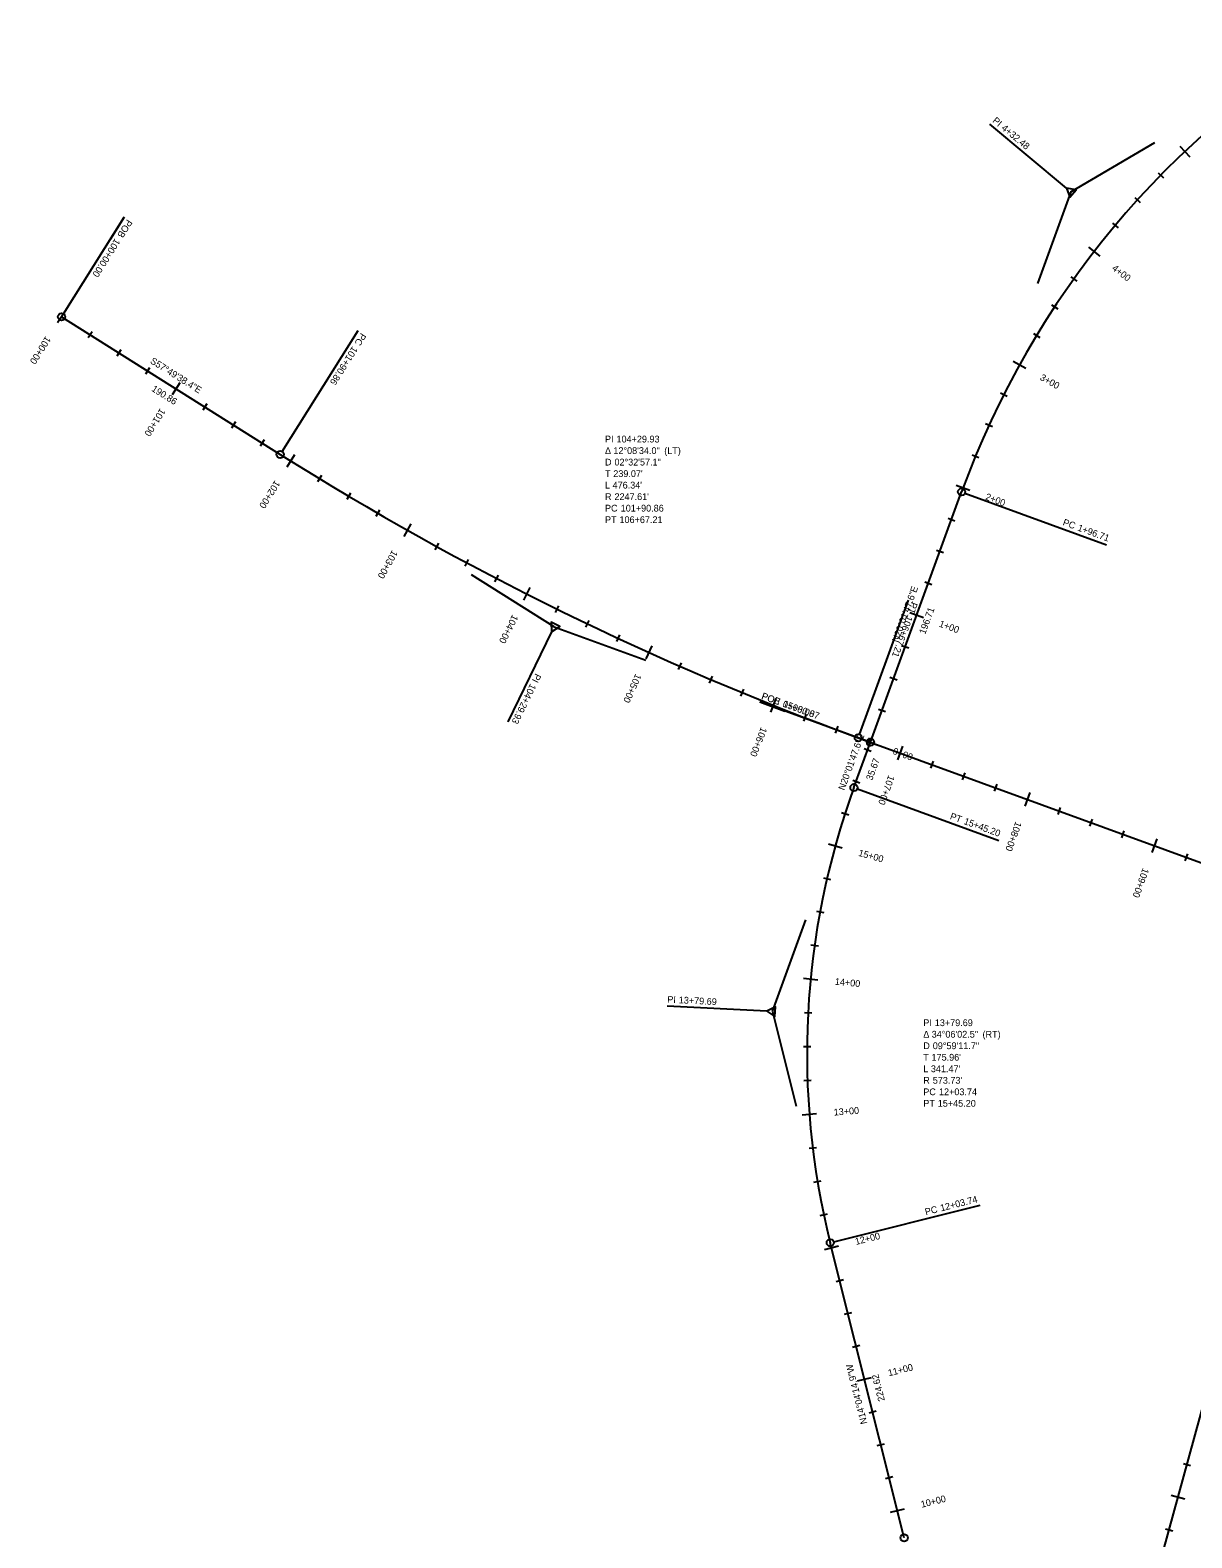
# Model space of a CAD drawing. Extents: x 2300830 to 2307917, y 756066 to 766359.
# Drawn here: x 2301963 to 2302821, y 761001 to 762114 of the extents above; entities that cross this region are included whole.
import ezdxf

# ---------------------------------------------------------------- set-up
doc = ezdxf.new("R2010")
doc.units = 0
for name, color, linetype in [('Default', 7, 'Continuous'), ('Draft_Bearing Label', 7, 'Continuous'), ('Draft_Curve Data Label', 7, 'Continuous'), ('Draft_Station Cardinal Lines', 7, 'Continuous'), ('Draft_Station Cardinal Points', 7, 'Continuous'), ('Draft_Station Labels Major', 7, 'Continuous'), ('Draft_Station Ticks Major', 7, 'Continuous'), ('Draft_Station Ticks Minor', 7, 'Continuous'), ('Geom_Baseline', 7, 'Continuous')]:
    doc.layers.add(name, color=color, linetype=linetype)

msp = doc.modelspace()

# ---------------------------------------------------------------- linework, layer by layer
at = {"layer": 'Default'}
for p, q in [((2301986.3, 761902.1), (2302147.8, 761800.5)), ((2302583.7, 761588), (2302651.1, 761772.8)), ((2302571.6, 761554.5), (2302583.8, 761588)), ((2302574.8, 761591.3), (2304125.3, 761026)), ((2302467.6, 759777.2), (2302927, 761454.4)), ((2302608.7, 761000.6), (2302554.1, 761218.5))]:
    msp.add_line(p, q, dxfattribs=at)
for centre, radius, start, end in [((2303267.1, 761548.3), 655.7, 120.4148, 159.9701), ((2303344.6, 763703), 2247.6, 237.8273, 249.9701), ((2303110.6, 761358), 573.7, 159.9701, 194.0708)]:
    msp.add_arc(centre, radius, start, end, dxfattribs=at)
at = {"layer": 'Draft_Station Cardinal Lines'}
for p, q in [((2302728.6, 761997), (2302671.9, 762044.3)), ((2302731.8, 761994.4), (2302793.9, 762030.8)), ((2302731.8, 761994.4), (2302707.2, 761926.7)), ((2302149.2, 761802.7), (2302205.3, 761891.9)), ((2302653.6, 761771.9), (2302758.2, 761733.8)), ((2302350.2, 761673.2), (2302289.2, 761711.5)), ((2302575.7, 761593.8), (2302611.8, 761692.8)), ((2302350.2, 761673.2), (2302417.8, 761648.5)), ((2302348.3, 761669.4), (2302315.9, 761603.1)), ((2302574.1, 761553.6), (2302678.7, 761515.4)), ((2302511.3, 761389.2), (2302536, 761456.8)), ((2302507.2, 761389.4), (2302433.5, 761393.2)), ((2302511.3, 761389.2), (2302528.9, 761319.3)), ((2302556.7, 761219.1), (2302664.7, 761246.2))]:
    msp.add_line(p, q, dxfattribs=at)
for points in [[(2302728.6, 761997), (2302731.1, 761990.3), (2302735.7, 761995.8)], [(2302348.3, 761669.4), (2302354.3, 761673.5), (2302347.9, 761676.6)], [(2302507.2, 761389.4), (2302513.2, 761385.5), (2302513.6, 761392.7)]]:
    msp.add_lwpolyline(points, close=True, dxfattribs=at)
at = {"layer": 'Draft_Station Cardinal Points'}
for p, q in [((2302671.9, 762044.3), (2302671.9, 762044.3)), ((2302731.8, 761994.4), (2302731.8, 761994.4)), ((2301987.7, 761904.4), (2302032.6, 761975.7)), ((2302032.6, 761975.7), (2302022.1, 761959.1)), ((2301986.3, 761902.1), (2301986.3, 761902.1)), ((2302205.3, 761891.9), (2302205.3, 761891.9)), ((2302147.8, 761800.5), (2302147.8, 761800.5)), ((2302651.1, 761772.8), (2302651.1, 761772.8)), ((2302758.2, 761733.8), (2302758.2, 761733.8)), ((2302611.8, 761692.8), (2302611.8, 761692.8)), ((2302350.2, 761673.2), (2302350.2, 761673.2)), ((2302581.2, 761588.9), (2302502, 761617.8)), ((2302502, 761617.8), (2302520.5, 761611.1)), ((2302581.3, 761588.9), (2302502.1, 761617.8)), ((2302502.1, 761617.8), (2302520.6, 761611)), ((2302315.9, 761603.1), (2302315.9, 761603.1)), ((2302574.8, 761591.3), (2302574.8, 761591.3)), ((2302583.7, 761588), (2302583.7, 761588)), ((2302583.8, 761588), (2302583.8, 761588)), ((2302571.6, 761554.5), (2302571.6, 761554.5)), ((2302678.7, 761515.4), (2302678.7, 761515.4)), ((2302433.5, 761393.2), (2302433.5, 761393.2)), ((2302511.3, 761389.2), (2302511.3, 761389.2)), ((2302664.7, 761246.2), (2302664.7, 761246.2)), ((2302554.1, 761218.5), (2302554.1, 761218.5)), ((2302608.7, 761000.6), (2302608.7, 761000.6))]:
    msp.add_line(p, q, dxfattribs=at)
for centre in [(2301986.3, 761902.1), (2302147.8, 761800.5), (2302651.1, 761772.8), (2302574.8, 761591.3), (2302583.7, 761588), (2302583.8, 761588), (2302571.6, 761554.5), (2302554.1, 761218.5), (2302608.7, 761000.6)]:
    msp.add_circle(centre, 2.67, dxfattribs=at)
at = {"layer": 'Draft_Station Ticks Major'}
for p, q in [((2302812.4, 762028), (2302819.7, 762020.3)), ((2302744.8, 761953.4), (2302753.1, 761946.9)), ((2301989.1, 761906.6), (2301983.4, 761897.6)), ((2302689.3, 761869.3), (2302698.6, 761864.1)), ((2302073.7, 761853.4), (2302068.1, 761844.4)), ((2302158.4, 761800.2), (2302152.8, 761791.1)), ((2302647.2, 761777.8), (2302657.2, 761774.1)), ((2302244.2, 761749.3), (2302239, 761740)), ((2302332.2, 761702.3), (2302327.4, 761692.8)), ((2302612.9, 761683.8), (2302622.9, 761680.2)), ((2302422.2, 761659.2), (2302417.8, 761649.5)), ((2302514, 761620.2), (2302510, 761610.3)), ((2302578.7, 761589.9), (2302588.7, 761586.2)), ((2302607.4, 761585.1), (2302603.8, 761575.1)), ((2302701.4, 761550.8), (2302697.7, 761540.8)), ((2302795.3, 761516.6), (2302791.7, 761506.6)), ((2302552.7, 761512.9), (2302562.9, 761510)), ((2302534.3, 761413.8), (2302544.8, 761412.7)), ((2302533.3, 761313), (2302543.9, 761313.8)), ((2302549.9, 761213.6), (2302560.2, 761216.1)), ((2302574.2, 761116.6), (2302584.5, 761119.1)), ((2302805.8, 761032.1), (2302816, 761029.3)), ((2302598.5, 761019.6), (2302608.8, 761022.1))]:
    msp.add_line(p, q, dxfattribs=at)
at = {"layer": 'Draft_Station Ticks Minor'}
for p, q in [((2302796.2, 762008.5), (2302800.2, 762004.7)), ((2302779, 761990.2), (2302783.1, 761986.5)), ((2302762.6, 761971.3), (2302766.8, 761967.8)), ((2302731.8, 761931.7), (2302736.3, 761928.4)), ((2302717.6, 761911), (2302722.2, 761907.9)), ((2302008.9, 761891.1), (2302005.9, 761886.5)), ((2302704.1, 761889.8), (2302708.9, 761886.9)), ((2302030, 761877.8), (2302027.1, 761873.1)), ((2302051.2, 761864.5), (2302048.3, 761859.8)), ((2302093.5, 761837.9), (2302090.6, 761833.2)), ((2302679.8, 761845.9), (2302684.7, 761843.4)), ((2302114.7, 761824.6), (2302111.8, 761819.9)), ((2302668.8, 761823.3), (2302673.9, 761821)), ((2302135.9, 761811.3), (2302132.9, 761806.6)), ((2302658.8, 761800.3), (2302663.9, 761798.2)), ((2302178.3, 761784.9), (2302175.4, 761780.2)), ((2302199.7, 761772), (2302196.9, 761767.3)), ((2302221.2, 761759.4), (2302218.5, 761754.6)), ((2302641.1, 761753.4), (2302646.2, 761751.5)), ((2302264.7, 761734.9), (2302262.1, 761730.1)), ((2302632.5, 761729.9), (2302637.7, 761728)), ((2302286.7, 761723), (2302284.1, 761718.1)), ((2302308.8, 761711.4), (2302306.2, 761706.5)), ((2302623.9, 761706.4), (2302629.1, 761704.5)), ((2302353.3, 761688.8), (2302350.9, 761683.9)), ((2302375.8, 761677.9), (2302373.4, 761672.9)), ((2302398.4, 761667.3), (2302396.1, 761662.3)), ((2302606.8, 761659.4), (2302612, 761657.6)), ((2302443.9, 761646.7), (2302441.7, 761641.7)), ((2302466.8, 761636.8), (2302464.7, 761631.7)), ((2302489.9, 761627.2), (2302487.8, 761622.1)), ((2302598.2, 761636), (2302603.4, 761634.1)), ((2302536.3, 761608.7), (2302534.3, 761603.5)), ((2302589.7, 761612.5), (2302594.9, 761610.6)), ((2302559.6, 761599.8), (2302557.7, 761594.7)), ((2302579.2, 761583.4), (2302584.4, 761581.5)), ((2302583, 761591.2), (2302581.2, 761586)), ((2302630, 761574.1), (2302628.1, 761568.9)), ((2302570.7, 761559.9), (2302575.9, 761558)), ((2302653.5, 761565.5), (2302651.6, 761560.3)), ((2302677, 761557), (2302675.1, 761551.8)), ((2302724, 761539.8), (2302722.1, 761534.7)), ((2302562.4, 761536.2), (2302567.7, 761534.5)), ((2302747.5, 761531.3), (2302745.6, 761526.1)), ((2302770.9, 761522.7), (2302769.1, 761517.5)), ((2302817.9, 761505.6), (2302816, 761500.4)), ((2302549, 761487.8), (2302554.3, 761486.6)), ((2302543.8, 761463.2), (2302549.3, 761462.2)), ((2302539.8, 761438.5), (2302545.3, 761437.7)), ((2302535, 761388.5), (2302540.5, 761388.2)), ((2302534.2, 761363.4), (2302539.7, 761363.3)), ((2302534.5, 761338.2), (2302540, 761338.4)), ((2302538.4, 761288.2), (2302543.9, 761288.8)), ((2302542, 761263.3), (2302547.4, 761264.2)), ((2302546.6, 761238.6), (2302552, 761239.8)), ((2302558.4, 761189.9), (2302563.8, 761191.3)), ((2302564.5, 761165.7), (2302569.9, 761167)), ((2302570.6, 761141.4), (2302575.9, 761142.8)), ((2302582.7, 761092.9), (2302588.1, 761094.3)), ((2302588.8, 761068.7), (2302594.2, 761070)), ((2302814.9, 761055.6), (2302820.2, 761054.1)), ((2302594.9, 761044.4), (2302600.3, 761045.8)), ((2302801.7, 761007.3), (2302807, 761005.9))]:
    msp.add_line(p, q, dxfattribs=at)
at = {"layer": 'Geom_Baseline'}
for p, q in [((2301986.3, 761902.1), (2302147.8, 761800.5)), ((2302583.7, 761588), (2302651.1, 761772.8)), ((2302571.6, 761554.5), (2302583.8, 761588)), ((2302574.8, 761591.3), (2304125.3, 761026)), ((2302467.6, 759777.2), (2302927, 761454.4)), ((2302608.7, 761000.6), (2302554.1, 761218.5))]:
    msp.add_line(p, q, dxfattribs=at)
for centre, radius, start, end in [((2303267.1, 761548.3), 655.7, 120.4148, 159.9701), ((2303344.6, 763703), 2247.6, 237.8273, 249.9701), ((2303110.6, 761358), 573.7, 159.9701, 194.0708)]:
    msp.add_arc(centre, radius, start, end, dxfattribs=at)

# ---------------------------------------------------------------- texts
at = {"layer": 'Draft_Bearing Label'}
for s, rotation, p in [('S57°49\'38.4"E', 327.8273, (2302051.3, 761868.2)), ('190.86', 327.8273, (2302052.3, 761847.7)), ('N20°01\'47.6"E', 69.9701, (2302604.2, 761661.3)), ('196.71', 69.9701, (2302624.2, 761667.3)), ('N20°01\'47.6"E', 69.9701, (2302564.5, 761552.1)), ('35.67', 69.9701, (2302585, 761559.4)), ('N14°04\'14.9"W', 104.0708, (2302581.5, 761085.2)), ('224.62', 104.0708, (2302594.5, 761102))]:
    msp.add_text(s, height=5, rotation=rotation, dxfattribs=at).set_placement(p)
at = {"layer": 'Draft_Curve Data Label'}
for s, p in [('Δ ', (2302387.7, 761800.8)), ('PI ', (2302387.7, 761809.3)), ('12°08\'34.0"', (2302393.9, 761800.8)), ('104+29.93', (2302396.2, 761809.3)), (' (LT)', (2302429.6, 761800.8)), ('D ', (2302387.7, 761792.3)), ('02°32\'57.1"', (2302394.7, 761792.3)), ('T ', (2302387.7, 761783.8)), ("239.07'", (2302393.8, 761783.8)), ('L ', (2302387.7, 761775.3)), ('R ', (2302387.7, 761766.8)), ("476.34'", (2302393.3, 761775.3)), ("2247.61'", (2302394.7, 761766.8)), ('PC ', (2302387.7, 761758.3)), ('101+90.86', (2302399.3, 761758.3)), ('PT ', (2302387.7, 761749.8)), ('106+67.21', (2302398.4, 761749.8)), ('PI ', (2302622.8, 761378.4)), ('13+79.69', (2302631.3, 761378.4)), ('Δ ', (2302622.8, 761369.9)), ('34°06\'02.5"', (2302629, 761369.9)), (' (RT)', (2302664.7, 761369.9)), ('D ', (2302622.8, 761361.4)), ('09°59\'11.7"', (2302629.8, 761361.4)), ('T ', (2302622.8, 761352.9)), ('L ', (2302622.8, 761344.4)), ("341.47'", (2302628.4, 761344.4)), ("175.96'", (2302628.9, 761352.9)), ('R ', (2302622.8, 761335.9)), ("573.73'", (2302629.8, 761335.9)), ('PC ', (2302622.8, 761327.4)), ('12+03.74', (2302634.4, 761327.4)), ('PT ', (2302622.8, 761318.9)), ('15+45.20', (2302633.5, 761318.9))]:
    msp.add_text(s, height=5, dxfattribs=at).set_placement(p)
at = {"layer": 'Draft_Station Cardinal Points'}
for s, rotation, p in [('PI ', 320.1924, (2302673.5, 762046.2)), ('4+32.48', 320.1924, (2302680.1, 762040.7)), ('POB ', 237.8273, (2302034.7, 761974.4)), ('100+00.00', 237.8273, (2302025.8, 761960.3)), ('PC', 237.8273, (2302207.4, 761890.6)), ('101+90.86', 237.8273, (2302201.2, 761880.7)), ('PC', 339.9701, (2302725.4, 761748.4)), ('1+96.71', 339.9701, (2302736.3, 761744.4)), ('PT', 249.9701, (2302614.1, 761691.9)), ('106+67.21', 249.9701, (2302610.4, 761681.7)), ('PI ', 243.8987, (2302336.3, 761639.2)), ('104+29.93', 243.8987, (2302332.6, 761631.6)), ('POB ', 339.9701, (2302502.8, 761620.2)), ('POE ', 339.9701, (2302502.9, 761620.1)), ('15+80.87', 339.9701, (2302518.6, 761614.4)), ('0+00.00', 339.9701, (2302518.5, 761614.4)), ('PT', 339.9701, (2302642.1, 761531.4)), ('15+45.20', 339.9701, (2302652.3, 761527.7)), ('PI ', 357.0205, (2302433.6, 761395.7)), ('13+79.69', 357.0205, (2302442.1, 761395.3)), ('12+03.74', 14.0708, (2302636, 761241.6)), ('PC', 14.0708, (2302624.7, 761238.7))]:
    msp.add_text(s, height=5, rotation=rotation, dxfattribs=at).set_placement(p)
at = {"layer": 'Draft_Station Labels Major'}
for s, rotation, p in [('4+00', 322.2059, (2302761.7, 761937.1)), ('100+00', 237.8273, (2301974.6, 761888.2)), ('3+00', 330.9441, (2302708.5, 761855.8)), ('101+00', 237.8273, (2302059.2, 761834.9)), ('102+00', 238.0602, (2302143.9, 761781.7)), ('2+00', 339.6823, (2302668.2, 761767.3)), ('103+00', 240.6094, (2302230.6, 761730.2)), ('104+00', 243.1586, (2302319.4, 761682.6)), ('1+00', 339.9701, (2302634, 761673.5)), ('105+00', 245.7077, (2302410.3, 761639)), ('106+00', 248.2569, (2302503, 761599.5)), ('0+00', 339.9701, (2302599.8, 761579.5)), ('107+00', 249.9701, (2302597.1, 761564)), ('108+00', 249.9701, (2302691, 761529.8)), ('15+00', 344.4843, (2302574.5, 761504.2)), ('109+00', 249.9701, (2302785, 761495.5)), ('14+00', 354.4708, (2302557.3, 761409)), ('13+00', 4.4574, (2302556.8, 761312.3)), ('12+00', 14.0708, (2302573.1, 761216.8)), ('11+00', 14.0708, (2302597.4, 761119.8)), ('10+00', 14.0708, (2302621.7, 761022.8))]:
    msp.add_text(s, height=5, rotation=rotation, dxfattribs=at).set_placement(p)

doc.saveas('drawing.dxf')
